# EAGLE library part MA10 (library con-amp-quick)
AMP QUICK CONNECTOR
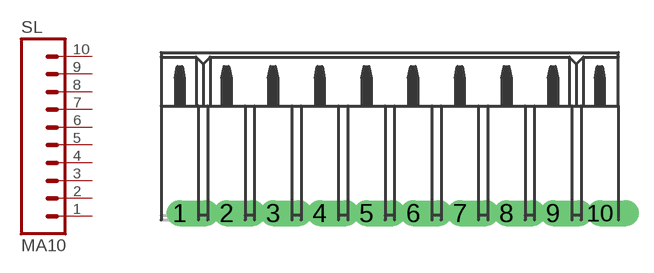
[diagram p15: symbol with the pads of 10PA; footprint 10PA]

Designator prefix SL

## MA10  [10PA]
1  1  pas
2  2  pas
3  3  pas
4  4  pas
5  5  pas
6  6  pas
7  7  pas
8  8  pas
9  9  pas
10  10  pas

## Footprint 10PA (pad centres in mm)
AMP QUICK CONNECTOR
drill 0.914 offset: 1 -11.43,0; 2 -8.89,0; 3 -6.35,0; 4 -3.81,0; 5 -1.27,0; 6 1.27,0; 7 3.81,0; 8 6.35,0; 9 8.89,0; 10 11.43,0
